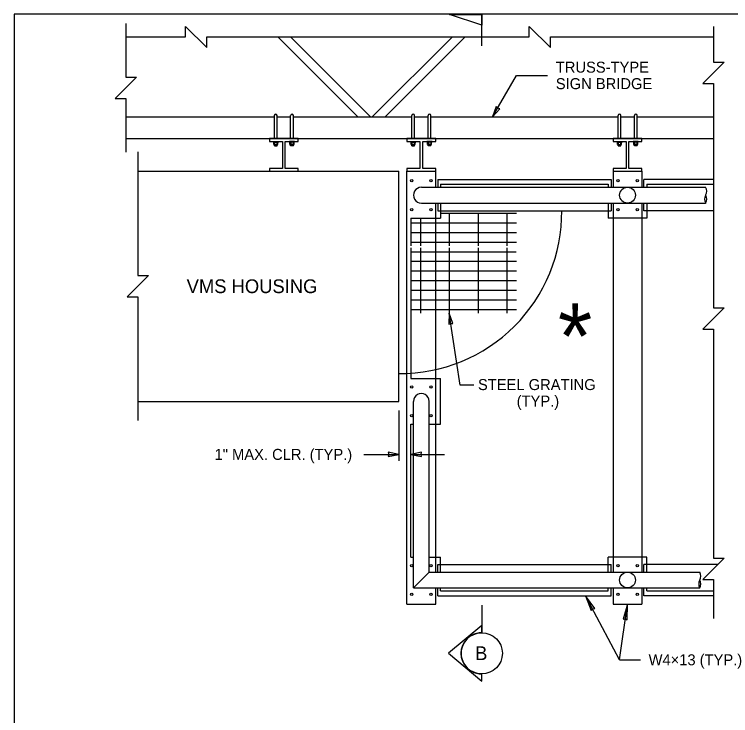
# Model space of a CAD drawing. Extents: x 99862 to 103151, y 100000 to 105076.
# Drawn here: x 99862 to 100904, y 104055 to 105076 of the extents above; entities that cross this region are included whole.
import ezdxf

# ---------------------------------------------------------------- set-up
doc = ezdxf.new("R2010")
doc.units = 0
for name, color, linetype in [('Level 1', 7, 'Continuous'), ('Level 15', 7, 'Continuous'), ('Level 2', 7, 'Continuous'), ('Level 20', 7, 'Continuous'), ('Level 4', 7, 'Continuous'), ('Level 5', 7, 'Continuous'), ('Level 7', 7, 'Continuous'), ('Level 9', 7, 'Continuous')]:
    doc.layers.add(name, color=color, linetype=linetype)

msp = doc.modelspace()

# ---------------------------------------------------------------- linework, layer by layer
at = {"layer": 'Level 1'}
msp.add_lwpolyline([(99862, 102999.5), (103151, 102999.5), (103151, 105075.5), (99862, 105075.5)], close=True, dxfattribs=at)
at = {"layer": 'Level 15'}
for p, q in [((100229.1, 105042.5), (100429.1, 105042.5)), ((100557.7, 104926.1), (100592.7, 104986.6)), ((100592.7, 104986.6), (100637.7, 104986.6)), ((100510.6, 104535.9), (100494.7, 104640.5)), ((100530.5, 104535.9), (100510.6, 104535.9)), ((100421.6, 104499), (100421.6, 104425.5)), ((100370.5, 104435.1), (100421.6, 104435.1)), ((100438.7, 104435.1), (100487.6, 104435.1)), ((100742.2, 104136.2), (100693.1, 104229.5)), ((100742.2, 104136.2), (100754.1, 104217.3)), ((100742.2, 104136.2), (100772.7, 104136.2))]:
    msp.add_line(p, q, dxfattribs=at)
for points in [[(100024.1, 105062), (100024.1, 104984), (100039.6, 104984), (100008.6, 104953), (100024.1, 104953), (100024.1, 104875)], [(100024.1, 105042.5), (100111.2, 105042.5), (100111.2, 105058), (100142.2, 105027), (100142.2, 105042.5), (100229.1, 105042.5)], [(100479.1, 105042.5), (100611, 105042.5), (100611, 105058), (100642, 105027), (100642, 105042.5), (100729.1, 105042.5)], [(100879.1, 105058), (100879.1, 105005.9), (100894.6, 105005.9), (100863.6, 104974.9), (100879.1, 104974.9), (100879.1, 104938.3)], [(100879.1, 104938.3), (100879.1, 104648.2), (100894.6, 104648.2), (100863.6, 104617.2), (100879.1, 104617.2), (100879.1, 104530.1)], [(100041.6, 104875.3), (100041.6, 104695.3), (100057.1, 104695.3), (100026.1, 104664.3), (100041.6, 104664.3), (100041.6, 104484.3)], [(100879.1, 104530.1), (100879.1, 104362.6)], [(100879.1, 104362.6), (100879.1, 104283.9), (100894.6, 104283.9), (100863.6, 104253), (100879.1, 104253), (100879.1, 104196.1)]]:
    msp.add_lwpolyline(points, dxfattribs=at)
for points in [[(100557.7, 104926.1), (100568.2, 104938.2), (100565.2, 104939.1), (100562.9, 104941.3)], [(100494.7, 104640.5), (100494, 104624.5), (100497, 104625.7), (100500.1, 104625.4)], [(100421.6, 104435.1), (100405.9, 104438.2), (100406.6, 104435.1), (100405.9, 104432)], [(100438.7, 104435.1), (100454.4, 104432), (100453.7, 104435.1), (100454.4, 104438.2)], [(100693.1, 104229.5), (100701.1, 104207.9), (100703.2, 104210.2), (100706.4, 104210.7)], [(100754.1, 104217.3), (100747.8, 104195.1), (100750.9, 104195.7), (100753.7, 104194.3)]]:
    msp.add_lwpolyline(points, close=True, dxfattribs=at)
for centre, start, end in [((100857.7, 104818), 330, 30), ((100877.7, 104806.5), 150, 210), ((100857.7, 104806.5), 330, 30), ((100849.1, 104258), 330, 30), ((100869.1, 104246.5), 150, 210), ((100849.1, 104246.5), 330, 30)]:
    msp.add_arc(centre, 11.5, start, end, dxfattribs=at)
at = {"layer": 'Level 2'}
for p, q in [((100229.1, 105042.5), (100279.1, 105042.5)), ((100429.1, 105042.5), (100479.1, 105042.5)), ((100729.1, 105042.5), (100879.1, 105042.5)), ((100275.1, 104894.6), (100233.1, 104894.6)), ((100233.1, 104894.6), (100233.1, 104890.6)), ((100233.1, 104890.6), (100251.9, 104890.6)), ((100251.9, 104890.6), (100251.9, 104851.3)), ((100256.1, 104851.3), (100256.1, 104890.6)), ((100256.1, 104890.6), (100275.1, 104890.6)), ((100275.1, 104890.6), (100275.1, 104894.6)), ((100475.1, 104894.6), (100433.1, 104894.6)), ((100433.1, 104894.6), (100433.1, 104890.6)), ((100433.1, 104890.6), (100451.9, 104890.6)), ((100451.9, 104890.6), (100451.9, 104851.3)), ((100456.1, 104851.3), (100456.1, 104890.6)), ((100456.1, 104890.6), (100475.1, 104890.6)), ((100475.1, 104890.6), (100475.1, 104894.6)), ((100775.1, 104894.6), (100733.1, 104894.6)), ((100733.1, 104894.6), (100733.1, 104890.6)), ((100733.1, 104890.6), (100751.9, 104890.6)), ((100751.9, 104890.6), (100751.9, 104851.3)), ((100756.1, 104851.3), (100756.1, 104890.6)), ((100756.1, 104890.6), (100775.1, 104890.6)), ((100775.1, 104890.6), (100775.1, 104894.6)), ((100041.6, 104847.3), (100421.6, 104847.3)), ((100251.9, 104851.3), (100233.1, 104851.3)), ((100233.1, 104851.3), (100233.1, 104847.3)), ((100233.1, 104847.3), (100275.1, 104847.3)), ((100275.1, 104851.3), (100256.1, 104851.3)), ((100275.1, 104847.3), (100275.1, 104851.3)), ((100421.6, 104512.3), (100421.6, 104847.3)), ((100451.9, 104851.3), (100433.1, 104851.3)), ((100433.1, 104851.3), (100433.1, 104847.3)), ((100433.1, 104847.3), (100475.1, 104847.3)), ((100475.1, 104851.3), (100456.1, 104851.3)), ((100475.1, 104847.3), (100475.1, 104851.3)), ((100751.9, 104851.3), (100733.1, 104851.3)), ((100733.1, 104851.3), (100733.1, 104847.3)), ((100733.1, 104847.3), (100775.1, 104847.3)), ((100775.1, 104851.3), (100756.1, 104851.3)), ((100775.1, 104847.3), (100775.1, 104851.3)), ((100041.6, 104512.3), (100421.6, 104512.3))]:
    msp.add_line(p, q, dxfattribs=at)
at = {"layer": 'Level 4'}
for p, q in [((100240.3, 104894.6), (100240.3, 104928.1)), ((100244.2, 104894.6), (100244.2, 104928.1)), ((100264, 104894.6), (100264, 104928.1)), ((100267.9, 104894.6), (100267.9, 104928.1)), ((100440.3, 104894.6), (100440.3, 104928.1)), ((100444.2, 104894.6), (100444.2, 104928.1)), ((100464, 104894.6), (100464, 104928.1)), ((100467.9, 104894.6), (100467.9, 104928.1)), ((100740.3, 104894.6), (100740.3, 104928.1)), ((100744.2, 104894.6), (100744.2, 104928.1)), ((100764, 104894.6), (100764, 104928.1)), ((100767.9, 104894.6), (100767.9, 104928.1)), ((100238.5, 104889.7), (100238.5, 104890.6)), ((100238.5, 104890.6), (100246.1, 104890.6)), ((100238.5, 104889.7), (100246.1, 104889.7)), ((100239.3, 104889.7), (100245.2, 104889.7)), ((100239.3, 104886.2), (100239.3, 104889.7)), ((100240.5, 104889.7), (100240.5, 104886.2)), ((100243.9, 104889.7), (100243.9, 104886.2)), ((100245.2, 104886.2), (100245.2, 104889.7)), ((100246.1, 104889.7), (100246.1, 104890.6)), ((100262.1, 104889.7), (100262.1, 104890.6)), ((100269.7, 104890.6), (100262.1, 104890.6)), ((100269.7, 104889.7), (100262.1, 104889.7)), ((100268.9, 104889.7), (100263, 104889.7)), ((100263, 104886.2), (100263, 104889.7)), ((100264.3, 104889.7), (100264.3, 104886.2)), ((100267.7, 104889.7), (100267.7, 104886.2)), ((100268.9, 104886.2), (100268.9, 104889.7)), ((100269.7, 104889.7), (100269.7, 104890.6)), ((100438.5, 104889.7), (100438.5, 104890.6)), ((100438.5, 104890.6), (100446.1, 104890.6)), ((100438.5, 104889.7), (100446.1, 104889.7)), ((100439.3, 104889.7), (100445.2, 104889.7)), ((100439.3, 104886.2), (100439.3, 104889.7)), ((100440.5, 104889.7), (100440.5, 104886.2)), ((100443.9, 104889.7), (100443.9, 104886.2)), ((100445.2, 104886.2), (100445.2, 104889.7)), ((100446.1, 104889.7), (100446.1, 104890.6)), ((100462.1, 104889.7), (100462.1, 104890.6)), ((100469.7, 104890.6), (100462.1, 104890.6)), ((100469.7, 104889.7), (100462.1, 104889.7)), ((100468.9, 104889.7), (100463, 104889.7)), ((100463, 104886.2), (100463, 104889.7)), ((100464.3, 104889.7), (100464.3, 104886.2)), ((100467.7, 104889.7), (100467.7, 104886.2)), ((100468.9, 104886.2), (100468.9, 104889.7)), ((100469.7, 104889.7), (100469.7, 104890.6)), ((100738.5, 104889.7), (100738.5, 104890.6)), ((100738.5, 104890.6), (100746.1, 104890.6)), ((100738.5, 104889.7), (100746.1, 104889.7)), ((100739.3, 104889.7), (100745.2, 104889.7)), ((100739.3, 104886.2), (100739.3, 104889.7)), ((100740.5, 104889.7), (100740.5, 104886.2)), ((100743.9, 104889.7), (100743.9, 104886.2)), ((100745.2, 104886.2), (100745.2, 104889.7)), ((100746.1, 104889.7), (100746.1, 104890.6)), ((100762.1, 104889.7), (100762.1, 104890.6)), ((100769.7, 104890.6), (100762.1, 104890.6)), ((100769.7, 104889.7), (100762.1, 104889.7)), ((100768.9, 104889.7), (100763, 104889.7)), ((100763, 104886.2), (100763, 104889.7)), ((100764.3, 104889.7), (100764.3, 104886.2)), ((100767.7, 104889.7), (100767.7, 104886.2)), ((100768.9, 104886.2), (100768.9, 104889.7)), ((100769.7, 104889.7), (100769.7, 104890.6)), ((100239.9, 104886), (100244.6, 104886)), ((100240.3, 104884.3), (100240.3, 104886)), ((100240.3, 104884.3), (100244.2, 104884.3)), ((100241.2, 104885.2), (100243.3, 104885.2)), ((100244.2, 104884.3), (100244.2, 104886)), ((100268.3, 104886), (100263.6, 104886)), ((100264, 104884.3), (100264, 104886)), ((100267.9, 104884.3), (100264, 104884.3)), ((100267, 104885.2), (100264.9, 104885.2)), ((100267.9, 104884.3), (100267.9, 104886)), ((100439.9, 104886), (100444.6, 104886)), ((100440.3, 104884.3), (100440.3, 104886)), ((100440.3, 104884.3), (100444.2, 104884.3)), ((100441.2, 104885.2), (100443.3, 104885.2)), ((100444.2, 104884.3), (100444.2, 104886)), ((100468.3, 104886), (100463.6, 104886)), ((100464, 104884.3), (100464, 104886)), ((100467.9, 104884.3), (100464, 104884.3)), ((100467, 104885.2), (100464.9, 104885.2)), ((100467.9, 104884.3), (100467.9, 104886)), ((100739.9, 104886), (100744.6, 104886)), ((100740.3, 104884.3), (100740.3, 104886)), ((100740.3, 104884.3), (100744.2, 104884.3)), ((100741.2, 104885.2), (100743.3, 104885.2)), ((100744.2, 104884.3), (100744.2, 104886)), ((100768.3, 104886), (100763.6, 104886)), ((100764, 104884.3), (100764, 104886)), ((100767.9, 104884.3), (100764, 104884.3)), ((100767, 104885.2), (100764.9, 104885.2)), ((100767.9, 104884.3), (100767.9, 104886)), ((100433.1, 104217.3), (100433.1, 104847.3)), ((100475.1, 104823.8), (100475.1, 104847.3)), ((100733.1, 104847.3), (100733.1, 104823.8)), ((100775.1, 104847.3), (100775.1, 104823.8)), ((100477.9, 104835.1), (100730.3, 104835.1)), ((100477.9, 104835.1), (100477.9, 104823.8)), ((100482.1, 104828.1), (100726.1, 104828.1)), ((100482.1, 104828.1), (100482.1, 104823.8)), ((100726.1, 104828.1), (100726.1, 104823.8)), ((100730.3, 104835.1), (100730.3, 104823.8)), ((100879.1, 104835.1), (100777.9, 104835.1)), ((100777.9, 104823.8), (100777.9, 104835.1)), ((100782.1, 104828.1), (100879.1, 104828.1)), ((100782.1, 104828.1), (100782.1, 104823.8)), ((100475.1, 104263.8), (100475.1, 104800.8)), ((100477.9, 104800.8), (100477.9, 104789.5)), ((100482.1, 104800.8), (100482.1, 104779.1)), ((100726.1, 104800.8), (100726.1, 104779.1)), ((100730.3, 104800.8), (100730.3, 104789.5)), ((100733.1, 104800.8), (100733.1, 104263.8)), ((100775.1, 104800.8), (100775.1, 104263.8)), ((100777.9, 104789.5), (100777.9, 104800.8)), ((100782.1, 104800.8), (100782.1, 104779.1)), ((100477.9, 104789.5), (100730.3, 104789.5)), ((100482.1, 104786.1), (100592.3, 104786.1)), ((100494.7, 104786.1), (100494.7, 104738.5)), ((100536.7, 104786.1), (100536.7, 104738.5)), ((100578.7, 104786.1), (100578.7, 104738.5)), ((100879.1, 104789.5), (100777.9, 104789.5)), ((100438.7, 104779.1), (100482.1, 104779.1)), ((100438.7, 104779.1), (100438.7, 104738.5)), ((100452.7, 104779.1), (100452.7, 104738.5)), ((100782.1, 104779.1), (100726.1, 104779.1)), ((100438.7, 104772.1), (100592.3, 104772.1)), ((100438.7, 104758.1), (100592.3, 104758.1)), ((100438.7, 104744.1), (100592.3, 104744.1)), ((100438.7, 104735.7), (100438.7, 104545.5)), ((100452.7, 104735.7), (100452.7, 104640.5)), ((100494.7, 104735.7), (100494.7, 104640.5)), ((100536.7, 104735.7), (100536.7, 104640.5)), ((100578.7, 104735.7), (100578.7, 104640.5)), ((100438.7, 104730.1), (100591.9, 104730.1)), ((100438.7, 104716.1), (100592.3, 104716.1)), ((100438.7, 104702.1), (100592.3, 104702.1)), ((100438.7, 104688.1), (100592.3, 104688.1)), ((100438.7, 104674.1), (100592.3, 104674.1)), ((100438.7, 104660.1), (100592.3, 104660.1)), ((100438.7, 104646.1), (100592.3, 104646.1)), ((100438.7, 104545.5), (100482.1, 104545.5)), ((100482.1, 104479.1), (100482.1, 104545.5)), ((100438.7, 104285.5), (100438.7, 104479.1)), ((100438.7, 104479.1), (100442.6, 104479.1)), ((100465.6, 104479.1), (100482.1, 104479.1)), ((100438.7, 104285.5), (100442.6, 104285.5)), ((100465.6, 104285.5), (100482.1, 104285.5)), ((100482.1, 104263.8), (100482.1, 104285.5)), ((100782.1, 104285.5), (100726.1, 104285.5)), ((100726.1, 104263.8), (100726.1, 104285.5)), ((100782.1, 104263.8), (100782.1, 104285.5)), ((100477.9, 104275.1), (100730.3, 104275.1)), ((100477.9, 104263.8), (100477.9, 104275.1)), ((100730.3, 104263.8), (100730.3, 104275.1)), ((100777.9, 104263.8), (100777.9, 104275.1)), ((100885.7, 104275.1), (100777.9, 104275.1)), ((100475.1, 104217.3), (100475.1, 104240.8)), ((100477.9, 104229.5), (100477.9, 104240.8)), ((100482.1, 104236.5), (100482.1, 104240.8)), ((100482.1, 104236.5), (100726.1, 104236.5)), ((100726.1, 104236.5), (100726.1, 104240.8)), ((100730.3, 104229.5), (100730.3, 104240.8)), ((100733.1, 104240.8), (100733.1, 104217.3)), ((100775.1, 104240.8), (100775.1, 104217.3)), ((100777.9, 104229.5), (100777.9, 104240.8)), ((100782.1, 104236.5), (100782.1, 104240.8)), ((100782.1, 104236.5), (100879.1, 104236.5)), ((100477.9, 104229.5), (100730.3, 104229.5)), ((100879.1, 104229.5), (100777.9, 104229.5)), ((100433.1, 104217.3), (100475.1, 104217.3)), ((100733.1, 104217.3), (100775.1, 104217.3))]:
    msp.add_line(p, q, dxfattribs=at)
for centre, radius in [((100440.1, 104833.3), 1.68), ((100468.1, 104833.3), 1.68), ((100740.1, 104833.3), 1.68), ((100768.1, 104833.3), 1.68), ((100754.1, 104812.3), 11.5), ((100440.1, 104791.3), 1.68), ((100468.1, 104791.3), 1.68), ((100740.1, 104791.3), 1.68), ((100768.1, 104791.3), 1.68), ((100440.1, 104533.3), 1.68), ((100468.1, 104533.3), 1.68), ((100440.1, 104491.3), 1.68), ((100468.1, 104491.3), 1.68), ((100440.1, 104273.3), 1.68), ((100468.1, 104273.3), 1.68), ((100740.1, 104273.3), 1.68), ((100768.1, 104273.3), 1.68), ((100754.1, 104252.3), 11.5), ((100440.1, 104231.3), 1.68), ((100468.1, 104231.3), 1.68), ((100740.1, 104231.3), 1.68), ((100768.1, 104231.3), 1.68)]:
    msp.add_circle(centre, radius, dxfattribs=at)
for centre, radius, start, end in [((100242.2, 104928.1), 1.97, 0, 180), ((100266, 104928.1), 1.97, 0, 180), ((100442.2, 104928.1), 1.97, 0, 180), ((100466, 104928.1), 1.97, 0, 180), ((100742.2, 104928.1), 1.97, 0, 180), ((100766, 104928.1), 1.97, 0, 180), ((100239.9, 104887.1), 1.08, 234.7199, 305.2801), ((100242.2, 104893.5), 7.44, 256.7504, 283.2496), ((100244.6, 104887.1), 1.08, 234.7199, 305.2801), ((100263.6, 104887.1), 1.08, 234.7199, 305.2801), ((100266, 104893.5), 7.44, 256.7504, 283.2496), ((100268.3, 104887.1), 1.08, 234.7199, 305.2801), ((100439.9, 104887.1), 1.08, 234.7199, 305.2801), ((100442.2, 104893.5), 7.44, 256.7504, 283.2496), ((100444.6, 104887.1), 1.08, 234.7199, 305.2801), ((100463.6, 104887.1), 1.08, 234.7199, 305.2801), ((100466, 104893.5), 7.44, 256.7504, 283.2496), ((100468.3, 104887.1), 1.08, 234.7199, 305.2801), ((100739.9, 104887.1), 1.08, 234.7199, 305.2801), ((100742.2, 104893.5), 7.44, 256.7504, 283.2496), ((100744.6, 104887.1), 1.08, 234.7199, 305.2801), ((100763.6, 104887.1), 1.08, 234.7199, 305.2801), ((100766, 104893.5), 7.44, 256.7504, 283.2496), ((100768.3, 104887.1), 1.08, 234.7199, 305.2801), ((100454.1, 104812.3), 11.5, 89.9981, 270.0019), ((100454.1, 104512.3), 11.5, 359.989, 180)]:
    msp.add_arc(centre, radius, start, end, dxfattribs=at)
at = {"layer": 'Level 5'}
for p, q in [((100454.1, 104823.8), (100867.7, 104823.8)), ((100454.1, 104800.8), (100867.7, 104800.8)), ((100442.6, 104240.8), (100442.6, 104512.3)), ((100465.6, 104263.8), (100465.6, 104512.3)), ((100465.6, 104263.8), (100442.6, 104240.8)), ((100465.6, 104263.8), (100859.1, 104263.8)), ((100442.6, 104240.8), (100859.1, 104240.8))]:
    msp.add_line(p, q, dxfattribs=at)
msp.add_arc((100423.4, 104787.8), 235, 269.5597, 0.423, dxfattribs=at)
at = {"layer": 'Level 7'}
for p, q in [((100245.3, 105042.5), (100361.7, 104926.1)), ((100263.9, 105042.5), (100380.3, 104926.1)), ((100499.2, 105042.5), (100382.8, 104926.1)), ((100517.7, 105042.5), (100401.3, 104926.1)), ((100024.1, 104926.1), (100240.3, 104926.1)), ((100244.2, 104926.1), (100264, 104926.1)), ((100267.9, 104926.1), (100440.3, 104926.1)), ((100444.2, 104926.1), (100464, 104926.1)), ((100467.9, 104926.1), (100740.3, 104926.1)), ((100744.2, 104926.1), (100764, 104926.1)), ((100767.9, 104926.1), (100879.1, 104926.1)), ((100024.1, 104894.6), (100879.1, 104894.6))]:
    msp.add_line(p, q, dxfattribs=at)
at = {"layer": 'Level 9'}
for p, q in [((100542, 105029.5), (100542, 105075)), ((100542, 104215.6), (100542, 104175.6)), ((100542, 104186.2), (100493.5, 104145.6)), ((100542, 104175.6), (100542, 104186.2)), ((100493.5, 104145.6), (100542, 104105)), ((100542, 104105), (100542, 104115.6))]:
    msp.add_line(p, q, dxfattribs=at)
msp.add_lwpolyline([(100542, 105059.5), (100495.1, 105075), (100542, 105075)], close=True, dxfattribs=at)
msp.add_circle((100542, 104145.6), 30, dxfattribs=at)
msp.add_arc((100542, 104145.6), 30, 89.9978, 270.0022, dxfattribs=at)

# ---------------------------------------------------------------- texts
at = {"layer": 'Level 20'}
for s, height, p in [('TRUSS-TYPE', 16, (100649.7, 104990.6)), ('SIGN BRIDGE', 16, (100649.7, 104966.6)), ('VMS HOUSING', 20, (100112.7, 104669.8)), ('*', 96, (100652.8, 104559.1)), ('STEEL GRATING', 16, (100536.5, 104528.7)), ('(TYP.)', 16, (100592.8, 104504.7)), ('1" MAX. CLR. (TYP.)', 16, (100153.3, 104427.1)), ('B', 20, (100532.3, 104135.8)), ('W4×13 (TYP.)', 16, (100784.7, 104128.2))]:
    msp.add_text(s, height=height, dxfattribs=at).set_placement(p)

doc.saveas('drawing.dxf')
